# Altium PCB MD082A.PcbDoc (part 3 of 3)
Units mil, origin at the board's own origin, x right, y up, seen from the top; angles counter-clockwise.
Board outline 3650 x 4750 mil, 4 copper layers (Top Layer, GND Layer, Power Layer, Bottom Layer), stack 61.2 mil thick; 201 components, 105 nets, 514 pads, 1209 vias.
Unrouted connection lines stored in the file: 46.
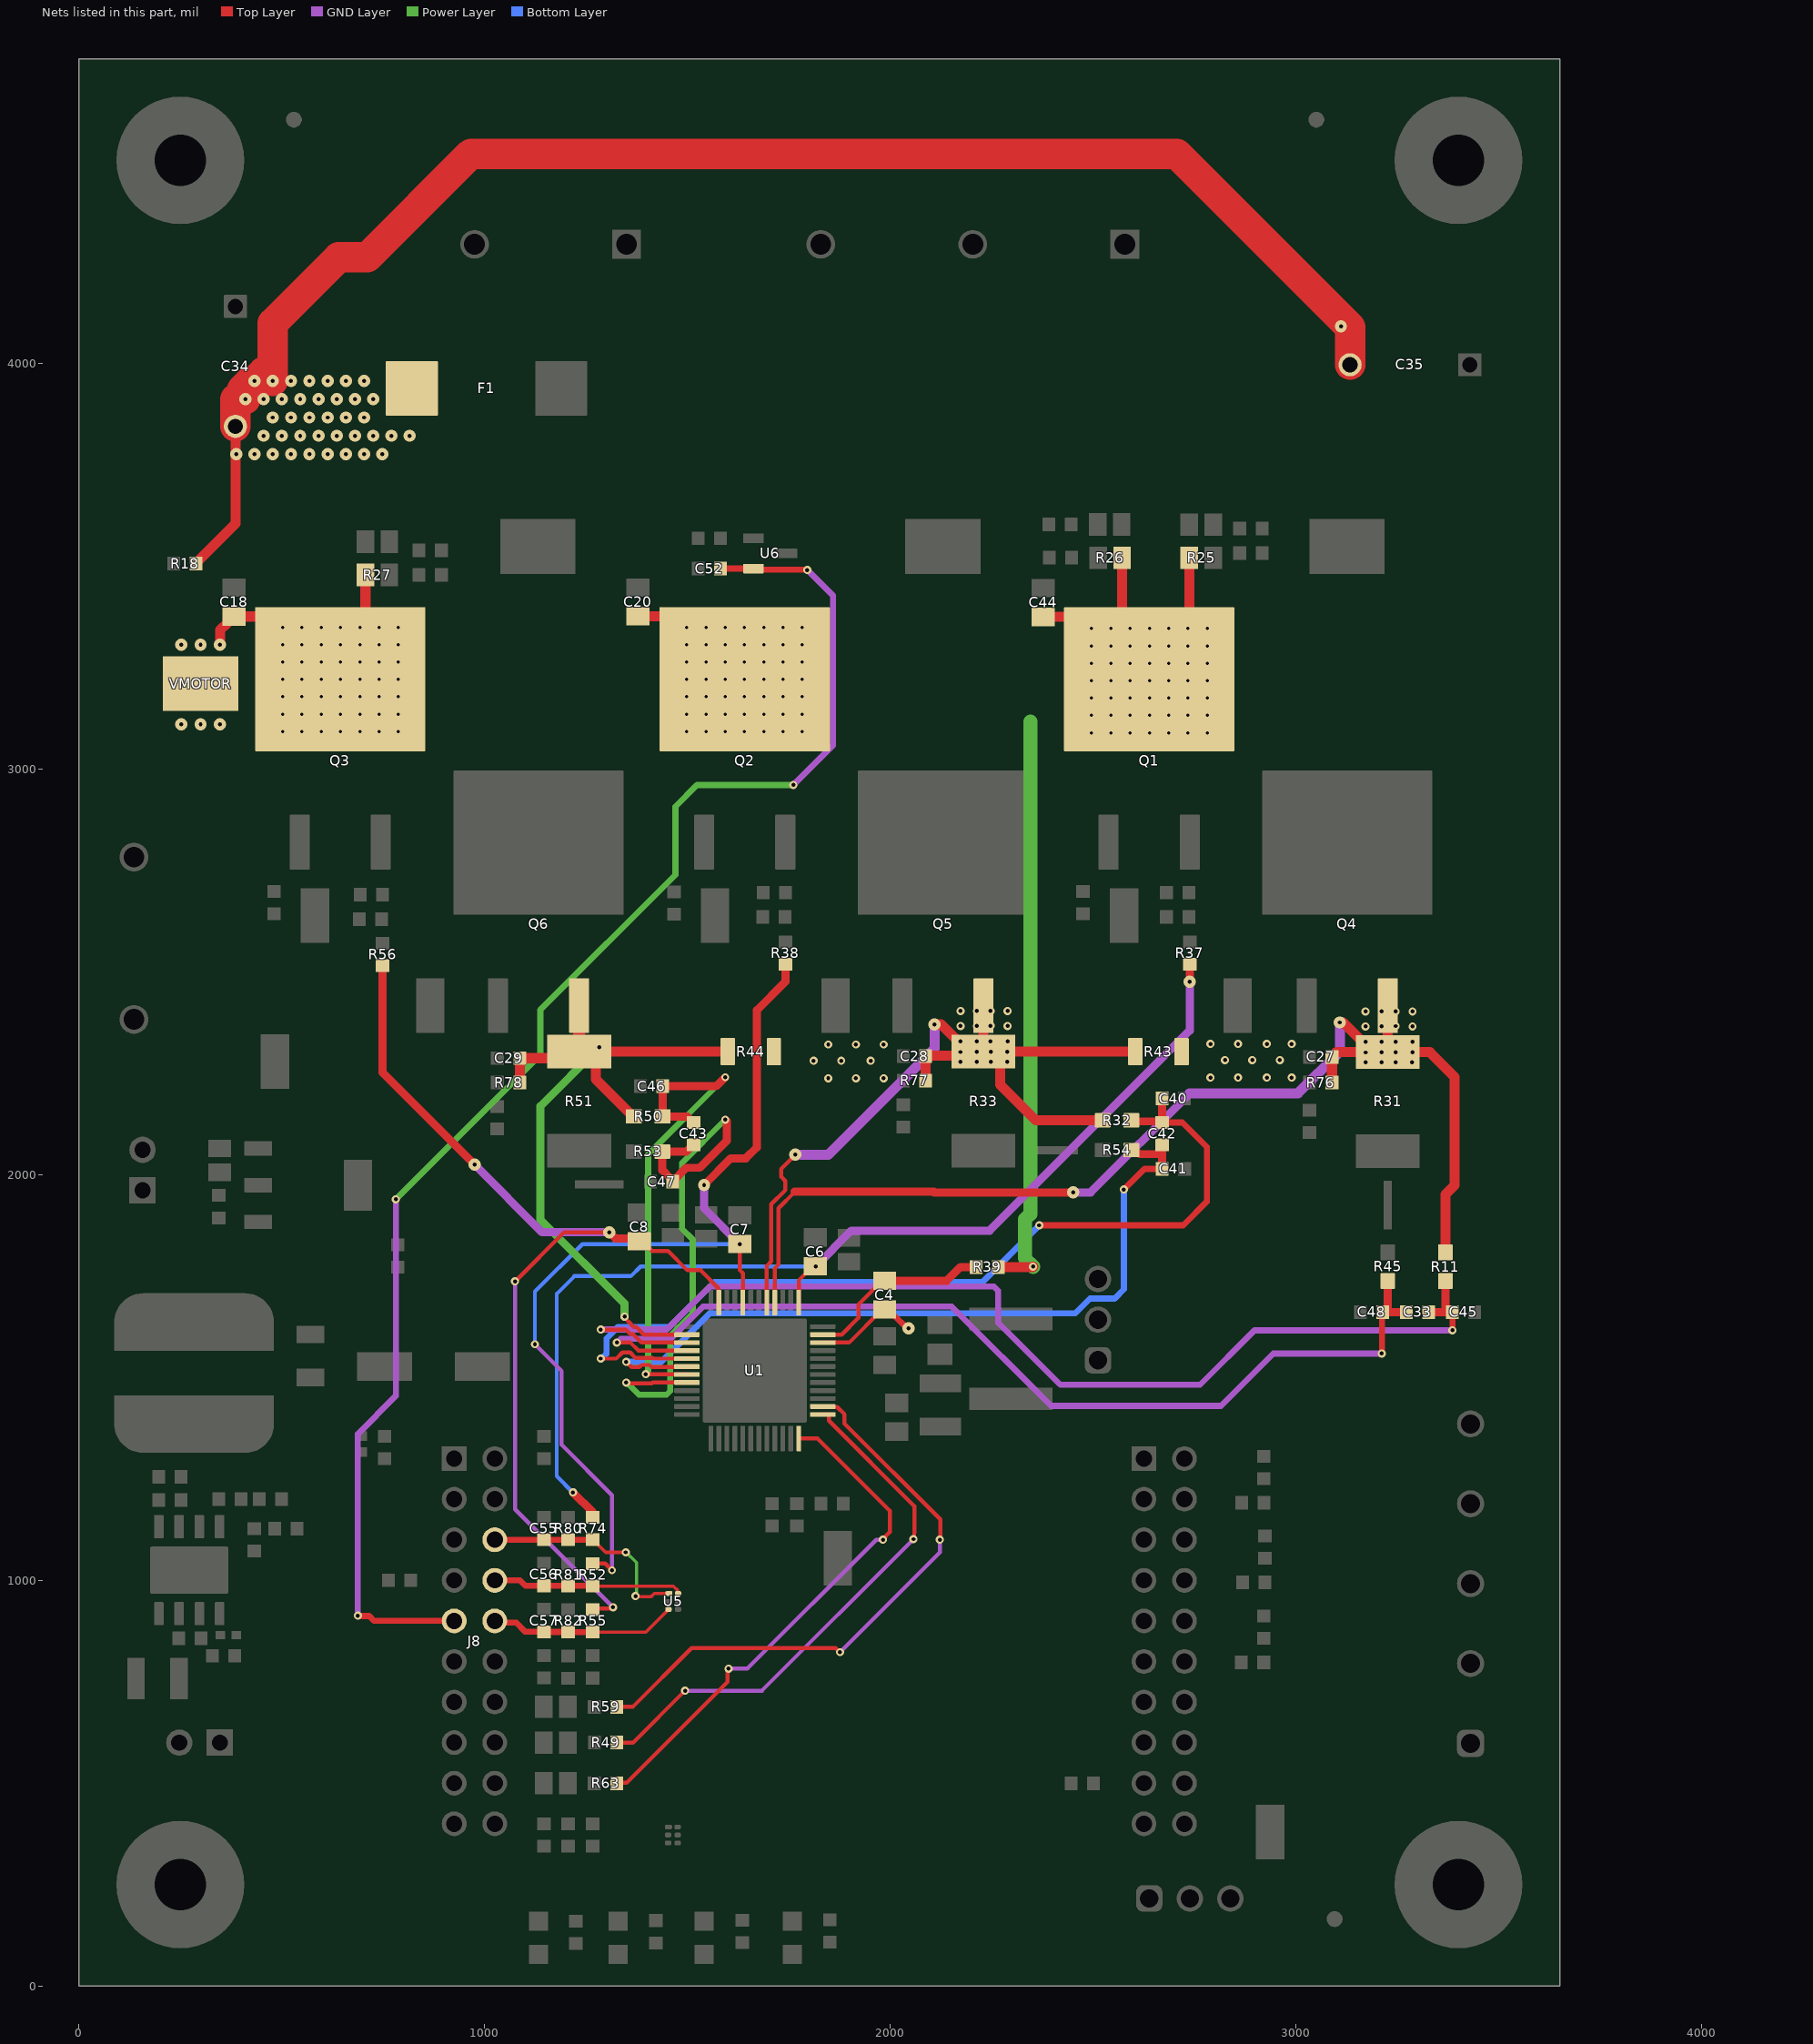
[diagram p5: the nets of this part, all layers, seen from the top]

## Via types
v1: diameter 20, hole 10, Top Layer to Bottom Layer, tented both sides, 424 vias
v2: diameter 30, hole 10, Top Layer to Bottom Layer, tented both sides, 355 vias
v3: diameter 30, hole 7.87, Top Layer to Bottom Layer, tented both sides, 294 vias
v4: diameter 19.68, hole 7.87, Top Layer to Bottom Layer, tented both sides, 76 vias
v5: diameter 20, hole 7.87, Top Layer to Bottom Layer, tented both sides, 54 vias
v6: diameter 19.68, hole 7.87, Top Layer to Bottom Layer, 4 vias
v7: diameter 20, hole 8, Top Layer to Bottom Layer, tented both sides, 1 vias
v8: diameter 30, hole 10, Top Layer to Bottom Layer, 1 vias

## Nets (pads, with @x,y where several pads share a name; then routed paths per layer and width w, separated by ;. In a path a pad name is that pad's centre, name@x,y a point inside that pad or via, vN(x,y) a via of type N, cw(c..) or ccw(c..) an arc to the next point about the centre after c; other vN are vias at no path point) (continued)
SHA: C6.1 R37.1 R74.2 U1.37 | length 2686
  Top Layer w10: U1.37@1775.17,1685.23 U1.37@1774.27,1684.32 1774.27,1739.4 C6.1@1809.24,1774.37
  Top Layer w20: v1(1217.84,1216.61) 1266.49,1167.95 R74.2@1266.49,1155.12 ; v2(2738,2475.67) R37.1@2738,2518.44
  GND Layer w20: v2(1815.77,1773.75) 1903.65,1861.63 2244.58,1861.63 2738,2355.04 v2(2738,2475.67)
  Bottom Layer w10: v1(1217.84,1216.61) 1177.71,1256.74 1177.71,1705.95 1221.4,1749.64 1360.37,1749.64 1384.48,1773.75 v2(1815.77,1773.75)
SHB: C7.1 R38.1 R52.2 U1.44 | length 2352.5
  Top Layer w10: R52.2@1266.49,1041.48 1297.34,1041.48 v1(1314,1024.81) ; v2(1629.31,1828.78) 1629.31,1764.1 1636.47,1756.95 U1.44@1636.47,1684.32
  Top Layer w20: v2(1541,1974) 1607,2040 1644,2040 1671,2067 1671,2405.11 1741.56,2475.67 R38.1@1741.56,2518.44
  GND Layer w10: v1(1123.91,1581.96) 1190,1515.87 1190,1334 1314,1210 v1(1314,1024.81)
  GND Layer w20: v2(1541,1974) 1541,1917.09 v2(1629.31,1828.78)
  Bottom Layer w10: v1(1123.91,1581.96) 1123.91,1711.91 1240.78,1828.78 v2(1629.31,1828.78)
SHC: C8.1 R55.2 R56.1 U1.47 | length 2586.1
  Top Layer w10: v1(1075,1736.71) 1196.29,1858 v2(1307,1858) ; R55.2@1266.49,927.56 1269.82,930.89 1313.67,930.89 v1(1316.53,933.74) ; C8.1@1380.86,1835.78 1398.5,1818.14 1407.11,1818.14 1413.09,1812.15 1451.55,1812.15 1499.57,1764.14 1532.38,1764.14 1576.51,1720.01 1576.51,1685.23 U1.47@1577.42,1684.32
  Top Layer w20: R56.1@748.56,2515.37 748.56,2251.22 v2(975,2024.78) ; v2(1307,1858) 1322.32,1842.68 1373.95,1842.68 C8.1@1380.86,1835.78
  GND Layer w10: v1(1075,1736.71) 1075,1175.27 v1(1316.53,933.74)
  GND Layer w20: v2(975,2024.78) 1141.78,1858 v2(1307,1858)
SLA: C27.2 Q4.3 R11.2 R31.2 R43.1 R76.2 U1.40 | length 2917.6
  Top Layer w10: U1.40@1715.21,1684.32 1715.21,1769.45 1724.35,1778.59 1724.35,1917 1763.99,1956.64 1763.99,1957.75
  Top Layer w20: 1763.99,1957.75 2106.62,1957.75 2108.37,1956 v2(2451,1956)
  Top Layer w25: R76.2@3088.56,2226.56 C27.2@3088.56,2290 3088.56,2290.98 3099.62,2302.05 R31.2@3188.6,2302.05 ; v2(3108,2375) 3115.65,2375 R31.2@3188.6,2302.05 ; Q4.3@3226,2416.43 R31.2@3226,2302.05 ; R11.2@3367.99,1808.31 3367.99,1951.08 3390.94,1974.02 3390.94,2240.62 3329.5,2302.05 R31.2@3226,2302.05 ; R31.2@3188.6,2302.05 R31.2@3226,2302.05
  GND Layer w20: v2(2451,1956) 2493.39,1956 2737.17,2199.78
  GND Layer w25: 2737.17,2199.78 3004.3,2199.78 3108,2303.48 v2(3108,2375)
  other v1: 2789,2239 2857,2239 2928,2239 2989.21,2239 3171,2277 3211,2277.29 3245.5,2276.9 3286,2276.9 2825,2282 2892,2282 2960,2282 3171,2301 3211,2302 3245.5,2302.05 3286.53,2302.05 2789,2322 2857,2322 2928,2322 2989,2322 3171,2327 3211,2327 3245,2327 3287,2327 3171,2365 3211,2365 3287,2365.25 3245,2366 3171,2402 3211,2402 3245,2402 3287,2402
SLB: C28.2 Q5.3 R32.2 R33.2 R43.2 R44.1 R77.2 U1.41 | length 2149.9
  Top Layer w10: U1.41@1695.53,1684.32 1695.53,1775.05 1706.48,1786 1706.48,1926.88 1741.12,1961.52 1741.12,1984.61 1730.96,1994.77 1730.96,2013.96 v2(1766,2049)
  Top Layer w25: R77.2@2087.12,2231.75 C28.2@2087.12,2292 ; C28.2@2087.12,2292.98 2219.44,2292.98 R33.2@2229.5,2303.05 ; v2(2109,2370) 2125.15,2370 2192.1,2303.05 2219.44,2303.05 R33.2@2229.5,2303.05 ; Q5.3@2229.5,2416.43 R33.2@2229.5,2303.05 ; R32.2@2523.09,2133.8 2358.19,2133.8 2270.62,2221.37 2270.62,2274.21 2241.78,2303.05 R33.2@2229.5,2303.05 ; R43.2@2603.58,2303.05 2266.9,2303.05 R33.2@2229.5,2303.05
  GND Layer w25: v2(1766,2049) 1846.95,2049 2109,2311.05 v2(2109,2370)
  other v1: 1847.03,2237.55 1915.31,2237.55 1983.31,2237.55 2173,2278.1 2213,2278.39 2247.5,2278 2288,2278 1811.03,2280.55 1879.03,2280.55 1951.31,2280.55 2173,2302.1 2213,2303.1 2247.5,2303.15 2288.53,2303.15 1847.03,2320.55 1915.31,2320.55 1983.31,2320.55 2173,2328.1 2213,2328.1 2247,2328.1 2289,2328.1 2173,2366.1 2213,2366.1 2289,2366.35 2247,2367.1 2173,2403.1 2213,2403.1 2247,2403.1 2289,2403.1
SLC: C29.2 Q6.3 R44.2 R50.2 R51.2 R78.2 U1.2 | length 1900.8
  Top Layer w10: v1(1345,1650) 1345,1647.29 1361.06,1631.24 1361.06,1630.47 1367.5,1624.02 1374.15,1624.02 1392.59,1605.58 U1.2@1498.68,1605.58
  Top Layer w25: R78.2@1086.56,2226.75 C29.2@1086.56,2287 1216.95,2287 R51.2@1233,2303.05 ; R50.2@1367.84,2143.35 1362.62,2148.57 1360.65,2148.57 1274.13,2235.1 1274.13,2274.21 1245.29,2303.05 R51.2@1233,2303.05 ; R44.2@1599.07,2303.05 1282.75,2303.05 R51.2@1233,2303.05
  Top Layer w30: R51.2@1233,2303.05 Q6.3@1233,2416.43
  Power Layer w20: v1(1282.75,2313.8) 1137.39,2168.44 1137.39,1889.42 1345,1681.81 v1(1345,1650)
SNA: C33.2 C48.1 R45.1 U1.4 | length 2483.1
  Top Layer w10: v1(1326.12,1585.9) 1359.38,1585.9 1378.66,1566.62 1421.28,1566.62 1421.69,1566.21 U1.4@1498.68,1566.21
  Top Layer w15: v1(3211,1559) 3211.96,1559.96 3211.96,1659.66 C48.1@3213.67,1661.37
  Top Layer w20: C48.1@3226,1661.27 3271.85,1661.27 C33.2@3271.95,1661.17 ; C48.1@3226,1661.37 R45.1@3226,1737.64
  GND Layer w15: v1(1326.12,1585.9) 1335.59,1595.37 1458.72,1595.37 1538.35,1675 2151.05,1675 2396.05,1430 2815,1430 2944,1559 v1(3211,1559)
SNB: C41.1 C42.2 R54.1 U1.6 | length 1966.1
  Top Layer w10: v1(1349,1538.65) 1362.2,1525.45 1381.63,1525.45 1387.05,1530.87 1406.47,1530.87 1411.9,1525.45 1462.51,1525.45 1462.99,1525.94 1497.77,1525.94 U1.6@1498.68,1526.84
  Top Layer w15: v1(2575.61,1963.31) 2626.39,2014.09 C41.1@2670.23,2014.09
  Top Layer w20: R54.1@2593.96,2060.39 2601.67,2052.68 2613.1,2052.68 2615.36,2050.41 2660.39,2050.41 C42.2@2670.23,2060.25 ; C41.1@2670.23,2014.09 C42.2@2670.23,2060.25 ; C42.2@2670.23,2073.35 C42.2@2670.23,2060.25
  Bottom Layer w15: v1(1349,1538.65) 1435.46,1538.65 1554.61,1657.8 2455.26,1657.8 2492.18,1694.72 2552.89,1694.72 2575.61,1717.44 v1(2575.61,1963.31)
SNC: C43.2 C47.1 R53.1 U1.8 | length 1421.1
  Top Layer w10: v1(1349,1487.61) 1351.71,1487.61 1354.19,1485.13 1412.01,1485.13 1414.36,1487.47 U1.8@1498.68,1487.47
  Top Layer w20: C43.2@1514.98,2073.34 1513.99,2073.34 1497.56,2056.91 R53.1@1438.21,2056.91 1438.21,2010.81 1458.02,1990.99 1458.02,1988.35 C47.1@1463.77,1982.61 1463.77,1983.59 1497.09,2016.91 1530.08,2016.91 1597.1,2083.93 1597.1,2131.61 v1(1593.17,2135.55)
  Power Layer w10: v1(1349,1487.61) v1@1350.35,1487.61
  Power Layer w15: v1@1350.35,1487.61 1380.46,1457.5 1448.6,1457.5 1457.39,1466.29 1457.39,1602.27 1512.89,1657.77 1512.89,1840.11 1486.61,1866.4 1486.61,2028.99 v1(1593.17,2135.55)
SOA: R59.2 U1.26 | length 1457.8
  Top Layer w10: R59.2@1325.34,688.06 1365.06,688.06 1510,833 1865.14,833 1875.14,823 v1(1876,823) ; U1.26@1833.32,1428.42 1834.23,1427.51 1869.01,1427.51 1886.88,1409.64 1886.88,1386.24 2123,1150.12 v1@2123,1104.72
  GND Layer w10: v1(1876,823) 2122,1069 v1(2122,1100)
SOB: R49.2 U1.25 | length 1348.4
  Top Layer w10: R49.2@1326.12,600 1366,600 v1(1494,728) ; U1.25@1833.32,1408.73 1847.46,1408.73 1848.37,1407.83 1848.37,1393.68 2059,1183.06 2059,1118.19 2058.91,1118.1 2058.91,1103.46 v1(2057,1101.54)
  GND Layer w10: v1(1494,728) 1683.46,728 v1(2057,1101.54)
SOC: R63.2 U1.24 | length 1299.1
  Top Layer w10: R63.2@1325.34,500 1326.55,501.21 1350.23,501.21 1599.13,750.1 1599.13,780.48 v1(1601.04,782.39) ; U1.24@1774.27,1349.68 1820.21,1349.68 1998.46,1171.42 1998.46,1118.7 1981.81,1102.05 v1(1981.81,1100)
  GND Layer w10: v1(1601.04,782.39) 1647.55,782.39 1965.16,1100 v1(1981.81,1100)
SPA: C33.1 C45.1 R11.1 U1.3 | length 2752.4
  Top Layer w10: v1(1286.42,1618.24) 1348,1618.24 1360.1,1606.15 1366.75,1606.15 1387,1585.9 U1.3@1498.68,1585.9
  Top Layer w15: 3367.99,1661.17 C45.1@3373.7,1661.17 ; 3367.99,1666.88 C45.1@3373.7,1661.17 ; v1(3385.34,1616.13) C45.1@3385.34,1661.17 C45.1@3373.7,1661.17
  Top Layer w20: C33.1@3327.06,1661.17 3367.99,1661.17 ; 3367.99,1666.88 R11.1@3367.99,1737.44
  GND Layer w15: v1(1286.42,1618.24) 1449.24,1618.24 1555.09,1724.09 2255.71,1724.09 2265.81,1714 2265.81,1635.19 2419,1482 2763.44,1482 2897.58,1616.13 v1(3385.34,1616.13)
SPB: C40.1 C42.1 R32.1 U1.5 | length 2306.9
  Top Layer w10: v1(1286.42,1546.53) 1324.53,1546.53 1339.53,1561.53 1358.47,1561.53 1371.25,1548.75 1413.88,1548.75 1416.1,1546.53 U1.5@1498.68,1546.53
  Top Layer w15: v1(2367,1875) 2721.87,1875 2780,1933.13 2780,2068.28 2719.81,2128.47 C42.1@2670.23,2128.47 2668.04,2130.65 C42.1@2667.56,2131.13
  Top Layer w20: R32.1@2593.96,2133.8 2596.62,2131.13 C42.1@2667.56,2131.13 ; C42.1@2668.04,2130.65 2669.81,2132.42 2669.81,2187.32 C40.1@2669.4,2187.73
  Bottom Layer w10: v1(1286.42,1546.53) v1@1288.78,1546.53
  Bottom Layer w15: v1@1288.78,1546.53 1300.74,1558.49 1300.74,1596.41 1328.96,1624.63 1455.63,1624.63 1566.23,1735.23 2227.23,1735.23 v1(2367,1875)
SPC: C43.1 C46.1 R50.1 U1.7 | length 1235.3
  Top Layer w10: v1(1397,1508) 1397.42,1507.58 1498.26,1507.58 U1.7@1498.68,1507.16
  Top Layer w20: C43.1@1514.98,2128.46 1513.99,2128.46 1499.1,2143.35 R50.1@1438.71,2143.35 1438.84,2143.49 1438.84,2217.52 C46.1@1438.98,2217.66 1570.66,2217.66 v1(1593,2240)
  Power Layer w15: v1(1397,1508) 1397,1509.35 1403.16,1515.51 1403.16,2050.16 v1(1593,2240)
TEMP: C52.1 J8.9 U6.2 | length 3686
  Top Layer w15: v1(687.61,912.96) 688.56,912.01 715.6,912.01 727.61,900 J8.9@925,900 ; C52.1@1581.47,3493.6 U6.2@1662.66,3493.6 1665.07,3491.19 1794.42,3491.19 v1(1795.38,3490.23)
  GND Layer w15: v1(687.61,912.96) 687.61,1360.65 781.22,1454.26 v1(781.22,1939.22) ; v1(1760.83,2960.27) 1859,3058.44 1859,3426.61 v1(1795.38,3490.23)
  Power Layer w15: v1(781.22,1939.22) 1137.39,2295.4 1137.39,2406 1470.12,2738.73 1470.12,2907 1523.39,2960.27 v1(1760.83,2960.27)
VCP: C4.1 U1.34 | length 264.7
  Top Layer w10: U1.34@1833.32,1585.9 1898.43,1585.9 1980.09,1667.57 C4.1@1986,1667.57
  Top Layer w15: C4.1@1986,1667.57 2001.14,1652.43 2009.82,1652.43 2040.94,1621.31 v8(2045,1621.31)
VDRAIN: C4.2 R39.1 U1.35 | length 466.1
  Top Layer w8: U1.35@1833.32,1605.58 U1.35@1838.27,1605.58
  Top Layer w10: U1.35@1838.27,1605.58 1879.82,1605.58 1921.14,1646.9 1921.14,1679.48 1980.09,1738.43 C4.2@1986,1738.43
  Top Layer w20: C4.2@1986,1738.43 2139.43,1738.43 2173,1772 R39.1@2211.44,1772
VMOTOR: C18.2 C20.2 C34.2 C35.2 C44.2 F1.1 Q1.2 Q2.2 Q3.2 R18.1 R25.2 R26.2 R27.2 R39.2 VMOTOR.1 | length 6242.6
  Top Layer w25: R18.1@288.56,3506 288.56,3506.98 386,3604.43 C34.2@386,3844.36 ; v2(347.5,3306.17) 348.46,3307.12 348.46,3342.02 365.96,3359.52 365.96,3365.43 376.09,3375.57 C18.2@382,3375.57 475.87,3375.57 v3(502.44,3349) ; v3(692.44,3349) 706.3,3362.86 R27.2@706.3,3478 ; C20.2@1378,3376 1471,3376 v3(1498,3349) ; R39.2@2266.56,1772 2350.84,1772 v1(2351.91,1773.07) ; C44.2@2377,3374.57 2467.43,3374.57 v3(2496,3346) ; R26.2@2571.04,3520.55 2571.04,3365.96 v3(2591,3346) ; v3(2733.5,3346) 2736.78,3349.28 R25.2@2736.78,3520.1
  Top Layer w30: Q3.2@520.46,3378.48 v3(549.94,3349)
  Top Layer w75: C34.2@386,3844.36 386,3911 ; v2(410.5,3911) 410.5,3926.63 402.09,3935.04 423.04,3956 v2(433,3956) 455.5,3978.5 ; v2(478,3956) 478,4098.63 640,4260.63 710.66,4260.63 966.04,4516 2705.87,4516 3133,4088.87 C35.2@3133,3996
  Power Layer w35: 2345,3116.05 2345,1903.03 2331.63,1889.65 2331.63,1793.36 v1(2351.91,1773.07)
  other v2: 252.5,3109.95 300,3109.95 347.5,3109.95 252.5,3306.17 300,3306.17 388,3776 433,3776 478,3776 523,3776 568,3776 613,3776 658,3776 703,3776 748,3776 455.5,3821 500.5,3821 545.5,3821 590.5,3821 635.5,3821 680.5,3821 725.5,3821 770.5,3821 815.5,3821 478,3866 523,3866 568,3866 613,3866 658,3866 703,3866 455.5,3911 500.5,3911 545.5,3911 590.5,3911 635.5,3911 680.5,3911 725.5,3911 523,3956 568,3956 613,3956 658,3956 703,3956 3110.5,4091
  other v3: 2496,3089 2543.5,3089 2591,3089 2638.5,3089 2686,3089 2733.5,3089 2781,3089 502.44,3092 549.94,3092 597.44,3092 644.94,3092 692.44,3092 739.94,3092 787.44,3092 1498,3092 1545.5,3092 1593,3092 1640.5,3092 1688,3092 1735.5,3092 1783,3092 2496,3131.83 2543.5,3131.83 2591,3131.83 2638.5,3131.83 2686,3131.83 2733.5,3131.83 2781,3131.83 502.44,3134.83 549.94,3134.83 597.44,3134.83 644.94,3134.83 692.44,3134.83 739.94,3134.83 787.44,3134.83 1498,3134.83 1545.5,3134.83 1593,3134.83 1640.5,3134.83 1688,3134.83 1735.5,3134.83 1783,3134.83 2496,3174.67 2543.5,3174.67 2591,3174.67 2638.5,3174.67 2686,3174.67 2733.5,3174.67 2781,3174.67 502.44,3177.67 549.94,3177.67 597.44,3177.67 644.94,3177.67 692.44,3177.67 739.94,3177.67 787.44,3177.67 1498,3177.67 1545.5,3177.67 1593,3177.67 1640.5,3177.67 1688,3177.67 1735.5,3177.67 1783,3177.67 2496,3217.5 2543.5,3217.5 2591,3217.5 2638.5,3217.5 2686,3217.5 2733.5,3217.5 2781,3217.5 502.44,3220.5 549.94,3220.5 597.44,3220.5 644.94,3220.5 692.44,3220.5 739.94,3220.5 787.44,3220.5 1498,3220.5 1545.5,3220.5 1593,3220.5 1640.5,3220.5 1688,3220.5 1735.5,3220.5 1783,3220.5 2496,3260.33 2543.5,3260.33 2591,3260.33 2638.5,3260.33 2686,3260.33 2733.5,3260.33 2781,3260.33 502.44,3263.33 549.94,3263.33 597.44,3263.33 644.94,3263.33 692.44,3263.33 739.94,3263.33 787.44,3263.33 1498,3263.33 1545.5,3263.33 1593,3263.33 1640.5,3263.33 1688,3263.33 1735.5,3263.33 1783,3263.33 2496,3303.17 2543.5,3303.17 2591,3303.17 2638.5,3303.17 2686,3303.17 2733.5,3303.17 2781,3303.17 502.44,3306.17 549.94,3306.17 597.44,3306.17 644.94,3306.17 692.44,3306.17 739.94,3306.17 787.44,3306.17 1498,3306.17 1545.5,3306.17 1593,3306.17 1640.5,3306.17 1688,3306.17 1735.5,3306.17 1783,3306.17 2543.5,3346 2638.5,3346 2686,3346 2781,3346 597.44,3349 644.94,3349 739.94,3349 787.44,3349 1545.5,3349 1593,3349 1640.5,3349 1688,3349 1735.5,3349 1783,3349
VSENA: C55.2 J8.6 R74.1 R80.2 U5.1 | length 542.6
  Top Layer w8: R74.1@1266.49,1100 1267.48,1100 1298.48,1069 v1(1348,1069) ; v1(1371.87,961.19) 1373.75,959.31 1409.72,959.31 1418.09,967.69 U5.1@1454.17,967.69
  Top Layer w15: J8.6@1025,1100 C55.2@1146,1100 R80.2@1206.25,1100 R74.1@1266.49,1100
  Power Layer w8: v1(1348,1069) 1349,1069 1374.17,1043.83 1374.17,963.49 v1(1371.87,961.19)
VSENB: C56.2 J8.8 R52.1 R81.2 U5.6 | length 469.1
  Top Layer w8: R52.1@1266.49,986.36 1267.39,985.46 1465.63,985.46 1474.91,976.19 1474.91,969.59 U5.6@1476.81,967.69
  Top Layer w15: J8.8@1025,1000 1087.11,1000 1100.63,986.48 1206.12,986.48 R81.2@1206.25,986.36 R52.1@1266.49,986.36
VSENC: C57.2 J8.10 R55.1 R82.2 U5.3 | length 463.9
  Top Layer w8: R55.1@1266.49,872.44 1397.32,872.44 1449.32,924.44 1449.32,926.41 1451.22,928.32 U5.3@1453.19,928.32
  Top Layer w15: J8.10@1025,900 1029.3,895.7 1078.01,895.7 1100.51,873.21 C57.2@1146,873.21 1146.38,872.82 1205.86,872.82 R82.2@1206.25,872.44 R55.1@1266.49,872.44
pads on no net: FID1.1 FID2.1 FID3.1 H1.0 H2.0 H3.0 H4.0 H5.1 H6.1 H7.1 H8.1 J8.3 J8.5 J8.11 J8.15 J9.6 J9.8 J9.10 J9.18 J9.19 J9.20 SH-J1.0 SH-J2.0 SH-J3.0 SH-J4.0 U2.6 U2.9@272,1025 U4.3 U4.4 U4.6

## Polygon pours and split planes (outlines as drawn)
SLB on Power Layer "POWER_LAYER_SLB_P078" (solid, remove dead copper, pour order 78): 2307.5,2431.7 2307.69,2431.51 2307.69,2262.67 2267.46,2222.44 1798.5,2222.44 1798.5,2336.18 1893.12,2430.8
SLA on Power Layer "POWER_LAYER_SLA_P086" (solid, remove dead copper, pour order 86): 3306.55,2262.01 3307,2262.46 3307,2416.89 2827,2416.89 2738.64,2328.54 2738.64,2227 3306.11,2227 3306.55,2226.56
VMOTOR on Power Layer "POWER_LAYER_VMOTOR_P110" (solid, remove dead copper, pour order 110): 308.69,3015 2899,3015 3289,3405 3289,4066 3212,4143 2968,4143 2818,3993 2654,3993 417.84,3993 230,3766.26 230,3071.31
GND on Power Layer "POWER_LAYER_GND_P068" (solid, remove dead copper, pour order 111): 0,4750 3650,4750 3650,0 0,0
MOTC on GND Layer "GND_LAYER_MOTC_P098" (solid, remove dead copper, pour order 98): 733,2556 839,2556 912.75,2629.75 1342.31,2629.75 1363,2650.44 1363,3206 1272,3297 1272,3420 1921,4069 1921,4314 1859,4376 1691,4376 878,3563 878,2836 767,2725 739,2725 733,2719
MOTA on GND Layer "GND_LAYER_MOTA_P100" (solid, remove dead copper, pour order 100): 2708,2558 2835.67,2558 2912.43,2634.75 3342.59,2634.75 3346.28,2638.45 3346.28,3657.22 2638,4365.5 2534.34,4365.5 2510.16,4341.32 2510.16,4005.84 2900.5,3615.5 2900.5,3024.22 2769.28,2893 2708,2893
MOTB on GND Layer "Top Layer-No Net" (solid, remove dead copper, pour order 99): 1838.27,2558 1915.03,2634.75 2348.38,2634.75 2355.07,2641.44 2355.07,3279.1 2328,3306.17 2328,3466 2343.1,3481.1 2391.7,3481.1 2407,3496.41 2407,3626.99 2387.92,3646.07 2387.92,3735.42 2387.92,4301.08 2307.68,4381.32 2091.49,4381.32 1974,4263.82 1974,4047.64 1919,3992.64 1919,3007 1819,2907 1722.16,2907 1718,2902.84 1718,2745.03 1725.07,2736.48 1725.07,2565.49 1721.86,2558
GND on GND Layer "GND_LAYER_GND_P066" (solid, remove dead copper, pour order 101): 0,4750 3650,4750 3650,0 0,0
GND on Bottom Layer "BOTTOM_LAYER_GND_P087" (solid, remove dead copper, pour order 87): -5.37,4724.31 3644.63,4724.31 3644.63,-25.69 -5.37,-25.69
VMOTOR on Bottom Layer "BOTTOM_LAYER_VMOTOR_P082" (solid, remove dead copper, pour order 82): 308.69,3015 2899,3015 3289,3405 3289,4066 3212,4143 2968,4143 2818,3993 2654,3993 434.29,3993 234,3770.7 234,3068.45
SLB on Top Layer "TOP_LAYER_SLB_P090" (solid, remove dead copper, pour order 90): 1695.53,2255.59 1733.46,2217.66 1975.52,2217.66 2006.18,2248.31 2005.74,2248.75 2005.74,2338.89 1697.38,2338.89 1695.53,2337.04
GND on Top Layer "GND_LAYER_GND_P066" (solid, remove dead copper, pour order 109): 0,4750 3650,4750 3650,0 0,0
SLB on Top Layer "TOP_LAYER_SLB_P091" (solid, remove dead copper, pour order 91): 2301.21,2343 2580.95,2343 2587.75,2336.2 2587.75,2270.01 2586.65,2270.01 2555.64,2239 2301.21,2239
SLA on Top Layer "TOP_LAYER_SLA_P092" (solid, remove dead copper, pour order 92): 2700.79,2270.01 2700.79,2254.01 2728.25,2226.56 3006.51,2226.56 3008.38,2228.43 3008.38,2338.69 3008.07,2339 2701,2339
SLA on Top Layer "TOP_LAYER_SLA_P093" (solid, remove dead copper, pour order 93): 3200.78,2483.7 3147,2429.91 3147,2337.51 3303.49,2337.51 3304,2337 3304,2430.7 3251,2483.7 3200.98,2483.7 3200.78,2483.89
SLB on Top Layer "TOP_LAYER_SLB_P094" (solid, remove dead copper, pour order 94): 2204.28,2484.7 2150.5,2430.91 2150.5,2338.51 2306.99,2338.51 2307.5,2338 2307.5,2431.7 2254.5,2484.7 2204.48,2484.7 2204.28,2484.89
SLC on Top Layer "TOP_LAYER_SLC_P102" (solid, remove dead copper, pour order 102): 1207.78,2484.7 1154,2430.91 1154,2338.51 1310.49,2338.51 1311,2338 1311,2431.7 1258,2484.7 1207.98,2484.7 1207.78,2484.89
SLC on Top Layer "TOP_LAYER_SLC_P089" (solid, remove dead copper, pour order 89): 1310.49,2383.49 1535.96,2383.49 1583.25,2336.2 1583.25,2270.01 1582.14,2270.01 1574.8,2262.67 1310.49,2262.67
VMOTOR on Top Layer "TOP_LAYER_VMOTOR_P103" (solid, remove dead copper, pour order 103): 886,4009 446.49,4009 319.09,3881.6 319.09,3792.23 355.31,3756 778.51,3756 882.75,3860.25
VMOTOR on Top Layer "TOP_LAYER_VMOTOR_P104" (solid, remove dead copper, pour order 104): 227.52,3327.52 191,3291 191,3129 232,3088 363,3088 405,3130 405,3302 380.53,3326.47
MOTC on Top Layer "TOP_LAYER_MOTC_P105" (solid, remove dead copper, pour order 105): 723.44,2556 839,2556 912.75,2629.75 1342.31,2629.75 1363,2650.44 1363,3206 1272,3297 1272,3420 1921,4069 1921,4314 1859,4376 1691,4376 878,3563 878,3043 723.44,2888.44
MOTB on Top Layer "Top Layer-MOTB" (solid, remove dead copper, pour order 107): 1838.27,2558 1915.03,2634.75 2348.38,2634.75 2355.07,2641.44 2355.07,3279.1 2328,3306.17 2328,3466 2343.1,3481.1 2391.7,3481.1 2407,3496.41 2407,3626.99 2387.92,3646.07 2387.92,3735.42 2387.92,4301.08 2307.68,4381.32 2091.49,4381.32 1974,4263.82 1974,4047.64 1919,3992.64 1919,3007 1819,2907 1722.16,2907 1718,2902.84 1718,2745.03 1725.07,2736.48 1725.07,2558
MOTA on Top Layer "TOP_LAYER_MOTA_P108" (solid, remove dead copper, pour order 108): 2708,2558 2835.67,2558 2912.43,2634.75 3342.59,2634.75 3346.28,2638.45 3346.28,3657.22 2638,4365.5 2534.34,4365.5 2510.16,4341.32 2510.16,4005.84 2900.5,3615.5 2900.5,3024.22 2769.28,2893 2708,2893

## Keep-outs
Keep-Out Layer:
  text ".Layer_Name" at 577,-858.49 h60

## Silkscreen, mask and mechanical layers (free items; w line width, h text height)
Top Overlay:
  circle w12: c848.76,1377.9 r5.51
  circle w12: c2550.97,1364.3 r5.51
  lines w10: 879,341 1072.03,340.03 1072.5,340.5 1072.5,1359.5 1072,1360 879,1360 879,342 ; 2577.5,339.03 2770.53,338.05 ; 2577.5,340.03 2577.5,1358.03 2770.5,1358.03 ; 2578.46,1625.37 2607.3,1625.37 2607.73,1527.79 2578.73,1527.79 ; 2578.46,1740.58 2607.3,1740.58 2607.73,1643 2578.73,1643 ; 2620.09,156.4 2620.09,127.4 2717.66,127.83 2717.66,156.67 ; 2758.91,155.1 2758.91,126.1 2856.49,126.52 2856.49,155.36 ; 2771,338.53 2771,1357.53
  text "GND" at 923.2,4034.86 h35
  text "VMOTOR" at 1243.2,4034.86 h35
  text "MOTC" at 1771.15,4031.86 h35
  text "MOTB" at 2148.15,4031.86 h35
  text "MOTA" at 2516,4032.22 h35
  text "ABS MAX: 30A" at 1433,3936.03 h35
  text "PVDD SEL" at 2594.01,1783.96 h30
  text "PVDD" at 2630.6,1682.11 h30
  text "PVDD BUCK" at 2630.04,1562.28 h30
  text "J8" at 879,1387 h30
  text "J9" at 2592,1384 h30
  text "GND" at 3104,1369 h30
  text "HALL_C" at 3011.83,1179.05 h30
  text "HALL_B" at 3011.83,994.17 h30
  text "HALL_A" at 3011.83,795.92 h30
  text "HALL_PWR" at 2960.24,581.42 h30
  text "HALL" at 2412.14,205.33 h40
  text "PWR" at 2412.14,146.33 h40
  text "SEL" at 2412.14,88.33 h40
  text "3.3V" at 2572,70 h40
  text "5V" at 2779.39,70 h40
  text "'.PRJ_Number'.PCB_Rev" at 467.58,60 h70
  text ".Layer_Name" at 577,-858.49 h60
Bottom Overlay:
  text ".Layer_Name" at 577,-858.49 h60
Top Paste:
  text ".Layer_Name" at 577,-858.49 h60
Bottom Paste:
  text ".Layer_Name" at 577,-858.49 h60
Top Solder:
  text ".Layer_Name" at 577,-858.49 h60
  text ".Layer_Name" at 577,-858.49 h60
Solder Side:
  text ".Layer_Name" at 577,-858.49 h60
Drill Guide:
  text ".Layer_Name" at 577,-858.49 h60
M1 Board Outline:
  the board outline again, w10
  text ".Layer_Name" at 577,-858.49 h60
M2 Board Dimensions:
  rectangle: 0,-275 125,-150
  rectangle: 125,-400 500,-275
  lines w7: 0,-275 1000,-275 ; 125,-400 125,-150 ; 250,-400 250,-150 ; 500,-400 500,-150 ; 750,-400 750,-150 ; 0,-400 1000,-400 1000,-150 0,-150 0,-400
  text ".Layer_Name" at 577,-858.49 h60
M3 3D STEP Top:
  text ".Layer_Name" at 577,-858.49 h60
M4 3D STEP Bottom:
  text ".Layer_Name" at 577,-858.49 h60
M5 Assembly Top:
  lines w10: -292,-930.17 6308,-930.17 ; -292,-726.83 6310,-726.83 ; -292,-523.5 -292,-1133.5 3713,-1133.5 6310,-1133.5 6310,-523.5 -291.5,-523.5 -291.5,-1133.5 1284,-1133.5 ; 2173,-1133.5 2173,-523.5 ; 3440,-726.83 3440,-523.5 ; 4280,-726.83 4280,-523.5 ; 4902,-1140 4902,-937.17
  text "COMPONENTS MARKED 'DNP' SHOULD NOT BE POPULATED." at 1153.5,-318.5 h60
  text "ASSEMBLY VARIANT:" at 1153,-434 h60
  text ".VariantName" at 2189,-434 h60
  text "PCB VIEWED FROM TOP SIDE" at -228.5,-655.67 h60
  text "BOARD #:" at 2248,-655.67 h60
  text ".PRJ_Number" at 2793.5,-655.67 h60
  text "REV:" at 3638,-655.67 h60
  text ".PCB_Rev" at 3929.5,-655.67 h60
  text "SVN REV:" at 4476,-655.67 h60
  text ".VersionControl_RevNumber" at 4982,-655.67 h60
  text "TID #:" at 2248,-859 h60
  text ".TID" at 2793.5,-859 h60
  text "PLOT NAME =" at -228.5,-1064.34 h60
  text ".plot_File_Name" at 577,-1064.34 h60
  text "GENERATED    :" at 2250,-1064.34 h60
  text ".Print_Date" at 3119.5,-1064.34 h60
  text ".Print_Time" at 3848.5,-1064.34 h60
  text "TEXAS INSTRUMENTS" at 5113,-1064.34 h60
M6 Assembly Bottom:
  lines w10: -292.5,-727.33 6309.5,-727.33 ; -290.5,-930.67 6309.5,-930.67 ; 1115.5,-1140.5 1115.5,-937.67 ; 1737.5,-727.33 1737.5,-524 ; 2577.5,-727.33 2577.5,-524 ; 3844.5,-1134 3844.5,-524 ; 4733.5,-1134 6309,-1134 6309,-524 -292.5,-524 -292.5,-1134 2304.5,-1134 6309.5,-1134 6309.5,-524
  text "COMPONENTS MARKED 'DNP' SHOULD NOT BE POPULATED." at 6102,-318 h60
  text ".VariantName" at 5058,-434 h60
  text "ASSEMBLY VARIANT:" at 6097,-434 h60
  text ".VersionControl_RevNumber" at 1035.5,-656.17 h60
  text "SVN REV:" at 1541.5,-656.17 h60
  text ".PCB_Rev" at 2088,-656.17 h60
  text "REV:" at 2379.5,-656.17 h60
  text ".PRJ_Number" at 3224,-656.17 h60
  text "BOARD #:" at 3769.5,-656.17 h60
  text "PCB VIEWED FROM BOTTOM SIDE" at 6246,-656.17 h60
  text ".TID" at 3224,-859.5 h60
  text "TID #:" at 3769.5,-859.5 h60
  text "TEXAS INSTRUMENTS" at 904.5,-1064.84 h60
  text ".Print_Time" at 2169,-1064.84 h60
  text ".Print_Date" at 2898,-1064.84 h60
  text "GENERATED    :" at 3767.5,-1064.84 h60
  text ".plot_File_Name" at 5440.5,-1064.84 h60
  text "PLOT NAME =" at 6246,-1064.84 h60
M9 Title Sheet:
  drawing of 57 lines, arcs and shapes, not listed
  text "1" at 739.84,8036.5 h70
  text "2" at 3235.5,8036.5 h70
  text "3" at 5724.84,8036.5 h70
  text "4" at 8231.51,8036.5 h70
  text "5" at 10730.5,8036.5 h70
  text "6" at 13235.5,8036.5 h70
  text "A" at -416.5,6893.5 h70
  text "A" at 14383.5,6893.5 h70
  text "B" at -416.5,4513.5 h70
  text "B" at 14383.5,4513.5 h70
  text "C" at -416.5,2138.5 h70
  text "C" at 14383.5,2138.5 h70
  text "PROJECT TITLE:" at 11343.5,277.5 h45
  text ".PRJ_Title" at 11393.5,144.17 h70
  text "DESIGNED FOR:" at 11343.5,-23.5 h45
  text ".PRJ_Customer" at 11393.5,-163.5 h70
  text "D" at -416.5,-231.5 h70
  text "D" at 14383.5,-231.5 h70
  text "FILE NAME:" at 11343.5,-323.5 h45
  text ".PCB_File_Name_No_Path" at 11393.5,-443.5 h70
  text "Texas Instruments (TI) and/or its licensors do not warrant the accuracy or completeness of this specification" at 6374,-605.34 h45
  text "ENGINEER:" at 11343.5,-613.5 h45
  text "LAYOUT BY:" at 12848.5,-613.5 h45
  text "or any information contained therein. TI and/or its licensors do not warrant that this design will meet" at 6329.01,-718 h45
  text ".PRJ_Engineer" at 11393.5,-768.49 h70
  text ".PCB_Layout" at 12899,-768.49 h70
  text "the specifications, will be suitable for your application or fit for any particular purpose, or will operate in" at 6329.01,-830.67 h45
  text ".Layer_Name" at 577,-858.49 h60
  text "ALTIUM DESIGNER VERSION:" at 12848.5,-923.5 h45
  text "an implementation. TI and/or its licensors do not warrant that the design is production worthy. You should" at 6329.01,-943.33 h45
  text "completely validate and test your design implementation to confirm the system functionality for your application." at 6374,-1056 h45
  text ".print_Scale" at 11393.5,-1056.83 h70
  text ".Application_BuildNumber" at 12899,-1056.83 h70
  text "1" at 739.84,-1263.5 h70
  text "2" at 3235.5,-1263.5 h70
  text "3" at 5724.84,-1263.5 h70
  text "4" at 8231.51,-1263.5 h70
  text "5" at 10730.5,-1263.5 h70
  text "6" at 13235.5,-1263.5 h70
M10 Fab Notes:
  drawing of 189 lines, arcs and shapes, not listed
  text "DESIGN INFORMATION" at 12382.02,6356.17 h60
  text "MIN. TRACK WIDTH:" at 11737.46,6224.05 h60
  text "8" at 12833.7,6224.05 h60
  text "MIL" at 12988.46,6224.05 h60
  text "MIN. CLEARANCE:" at 11737.46,6099.92 h60
  text "0.2" at 12773.7,6099.93 h60
  text "mm" at 12988.46,6099.92 h60
  text "MIN. VIA PAD SIZE:" at 11737.46,5975.8 h60
  text "24" at 12803.71,5975.8 h60
  text "MIL" at 12988.46,5975.8 h60
  text "0.05mm (2MIL)" at 12432.46,5845.9 h60
  text "MINIMUM ANNULAR RING" at 11408.23,5837.67 h60
  text "EXTERNAL" at 13140.46,5837.67 h60
  text "PER" at 11608.23,5727.55 h60
  text "IPC-D-275 CLASS 2 LEVEL C" at 11828.23,5727.54 h60
  text "MIL, HOLES" at 13316.46,5627.07 h60
  text "+/-" at 12924,5618.48 h60
  text "+/-" at 13778,5618.48 h60
  text "REGISTRATION TOLERANCES:" at 11408.23,5617.42 h60
  text "METAL" at 12608,5617.42 h60
  text "5" at 13184.2,5617.42 h60
  text "3" at 14017.2,5617.42 h60
  text "MIL" at 14133.46,5617.42 h60
  text "HOLE SIZE TOLERANCE (UNLESS OTHERWISE SPECIFIED):" at 11408.23,5519.1 h60
  text "+/-" at 13778,5516.23 h60
  text "3" at 14017.2,5515.17 h60
  text "MIL" at 14133.46,5515.17 h60
  text "MATERIAL:" at 11333.46,5377.52 h60
  text "FR-4 High Tg" at 12319.9,5249 h60
  text "X" at 12175.46,5241.01 h60
  text "FR-408" at 11754.46,5236.49 h60
  text "OTHER" at 13242.46,5236.49 h60
  text "62 MIL (1.6mm) +/-10%" at 12074.56,5093.46 h60
  text "X" at 11954.46,5091.01 h60
  text "THICKNESS:" at 11408.23,5085.24 h60
  text "OTHER" at 13359.46,5085.24 h60
  text "TOLERANCE:" at 11408.23,4946.92 h60
  text "X" at 12256.46,4946.92 h60
  text "ANSI IPC-6012 TYPE 3 CLASS 2" at 12434.48,4946.92 h60
  text "OTHER +/-" at 12434.46,4802.73 h60
  text "BOW & TWIST:" at 11408.23,4657.54 h60
  text "X" at 12256.46,4657.54 h60
  text "ANSI IPC-6012 TYPE 3 CLASS 2" at 12434.48,4657.54 h60
  text "OTHER +/-" at 12434.46,4510.85 h60
  text "DRILLING:" at 11333.46,4380.23 h60
  text "NC_DRILL FILES" at 13094.46,4275.04 h60
  text "REFERENCE:" at 11408.23,4271.1 h60
  text "X" at 12065.46,4271.01 h60
  text "AS SHOWN" at 12243.46,4271.1 h60
  text "X" at 12966.46,4271.1 h60
  text "OTHER" at 13392.46,4128.85 h60
  text "PTH COPPER THICKNESS:" at 11407.91,4125.32 h60
  text "X" at 12547.14,4125.32 h60
  text "20-30 um" at 12675.14,4125.32 h60
  text "BOARD FINISH:" at 11333.46,3977.73 h60
  text "SILKSCREEN:" at 11488.68,3867.6 h60
  text "X" at 12446.46,3867.6 h60
  text "TOP" at 12563.46,3867.6 h60
  text "X" at 12956.46,3867.6 h60
  text "BOTTOM" at 13074.46,3867.6 h60
  text "SILKSCREEN COLOR:" at 11488.68,3712.41 h60
  text "X" at 12445.46,3712.41 h60
  text "WHITE" at 12563.46,3712.41 h60
  text "OTHER" at 13074.46,3712.41 h60
  text "X" at 12576.46,3568.96 h60
  text "GREEN" at 12694.46,3568.96 h60
  text "OTHER" at 13312.46,3568.96 h60
  text "SOLDER RESIST COLOR:" at 11488.68,3562.1 h60
  text "X" at 12576.46,3414.71 h60
  text "MATTE" at 12694.46,3414.71 h60
  text "SEMI-GLOSS" at 13312,3414.07 h60
  text "IMMERSION GOLD (ENIG)" at 12394.46,3241.94 h60
  text "ENEPIG" at 13732,3234.72 h60
  text "SURFACE FINISH:" at 11333.46,3233.72 h60
  text "X" at 12216.46,3233.72 h60
  text "IMM. TIN/SILVER OR EQUIV" at 11663,3096.4 h60
  text "OTHER" at 13094.46,3092.47 h60
  text "ARRAY/PANEL:" at 11333.46,2937.09 h60
  text "CUT AND TRIM PER M1 BOARD OUTLINE" at 12394.46,2928.87 h60
  text "N.C. ROUTE" at 12394.46,2792.9 h60
  text "X" at 13082.46,2792.9 h60
  text "V. SCORE" at 13260.46,2792.9 h60
  text "CERTIFICATION:" at 11333.46,2663.77 h60
  text "MATERIALS AND WORKMANSHIP FOR ALL PCBS" at 12058.46,2663.77 h60
  text "TO MEET OR EXCEED THE REQUIREMENTS OF:" at 12058.46,2569.71 h60
  text "X" at 11695.97,2441.08 h60
  text "ANSI IPC-A-600F CLASS ->" at 11823.96,2441.08 h60
  text "X" at 13471.97,2441.08 h60
  text "2" at 13581.96,2441.08 h60
  text "1" at 13266.96,2439.58 h60
  text "3" at 13935.96,2439.58 h60
  text "X" at 12507.97,2293.39 h60
  text "RoHS" at 12635.96,2293.39 h60
  text "OTHER" at 13280.36,2293.39 h60
  text "PER ORDER" at 13677.42,2293.39 h60
  text "ALL BOARDS MUST MEET OR EXCEED UL94-V0 REQUIREMENTS." at 11361,2139.57 h60
  text "PCB MUST BEAR THE UL94V-0 UL REGISTERED MATERIAL ID NUMBER" at 11361,2023.5 h60
  text "ADDITIONAL REQUIREMENTS:" at 11333.46,1854.08 h60
  text "MICROSECTION:" at 11408.23,1746.95 h60
  text "YES" at 12313.96,1746.95 h60
  text "REQUIRED" at 13175.46,1602.62 h60
  text "BARE BOARD ELEC. TEST:" at 11408.23,1599.76 h60
  text "NONE" at 12713.96,1599.76 h60
  text "X" at 13057.46,1599.76 h60
  text "PER ORDER" at 13767.46,1599.76 h60
  text "XX MIL VIAS REQUIRE NON-CONDUCTIVE FILL AND PLANARIZE" at 11576.38,1394.82 h59
  text "XX MIL VIAS REQUIRE CONDUCTIVE FILL AND PLANARIZE" at 11584.38,1290.84 h60
  text "OUTER XX MIL TRACES REQUIRE 50 OHM SINGLE-ENDED IMPEDANCE" at 11583.39,1127.46 h58
  text "LAYER 2 & 3 (INNER LAYERS) XX MIL WIDE, XX MIL SPACE / TRACES REQUIRE 100 OHM DIFFERENTIAL IMPEDANCE" at 11575.39,891.74 h60
  text ".Layer_Name" at 577,-858.49 h60
M11 Gerber Information:
  lines w10: -292,-930.17 6308,-930.17 ; -292,-726.83 6310,-726.83 ; -292,-523.5 -292,-1133.5 3713,-1133.5 6310,-1133.5 6310,-523.5 -291.5,-523.5 -291.5,-1133.5 1284,-1133.5 ; 2173,-1133.5 2173,-523.5 ; 3440,-726.83 3440,-523.5 ; 4280,-726.83 4280,-523.5 ; 4902,-1140 4902,-937.17
  text "ALL ARTWORK VIEWED FROM TOP SIDE" at -228.5,-655.67 h60
  text "BOARD #:" at 2248,-655.67 h60
  text ".PRJ_Number" at 2793.5,-655.67 h60
  text "REV:" at 3638,-655.67 h60
  text ".PCB_Rev" at 3929.5,-655.67 h60
  text "SVN REV:" at 4476,-655.67 h60
  text ".VersionControl_RevNumber" at 4982,-655.67 h60
  text "LAYER NAME =" at -228.5,-858.49 h60
  text "TID #:" at 2248,-859 h60
  text ".TID" at 2793.5,-859 h60
  text "PLOT NAME =" at -228.5,-1064.34 h60
  text ".plot_File_Name" at 577,-1064.34 h60
  text "GENERATED    :" at 2250,-1064.34 h60
  text ".Print_Date" at 3119.5,-1064.34 h60
  text ".Print_Time" at 3848.5,-1064.34 h60
  text "TEXAS INSTRUMENTS" at 5113,-1064.34 h60
M12 Stackup:
  drawing of 295 lines, arcs and shapes, not listed
  text "Layer" at 6509.09,7318.5 h60
  text "Name" at 6919,7318.5 h60
  text "Material" at 7848.74,7318.5 h60
  text "Thickness" at 8708.51,7318.5 h60
  text "Constant" at 9358.35,7318.5 h60
  text "Board Layer Stack" at 9928.21,7318.5 h60
  text "1" at 6509.09,7198.5 h60
  text "Top Overlay" at 6919,7198.5 h60
  text "2" at 6509.09,7078.5 h60
  text "Top Solder" at 6919,7078.5 h60
  text "Solder Resist" at 7848.74,7078.5 h60
  text "0.40mil" at 8708.51,7078.5 h60
  text "3.5" at 9358.35,7078.5 h60
  text "3" at 6509.09,6958.5 h60
  text "Top Layer" at 6919,6958.5 h60
  text "Copper" at 7848.74,6958.5 h60
  text "2.80mil" at 8708.51,6958.5 h60
  text "4" at 6509.09,6838.5 h60
  text "Dielectric 2" at 6919,6838.5 h60
  text "FR-4 High Tg" at 7848.74,6838.5 h60
  text "10.00mil" at 8708.51,6838.5 h60
  text "4.8" at 9358.35,6838.5 h60
  text "5" at 6509.09,6718.5 h60
  text "GND Layer" at 6919,6718.5 h60
  text "Copper" at 7848.74,6718.5 h60
  text "1.40mil" at 8708.51,6718.5 h60
  text "6" at 6509.09,6598.5 h60
  text "Dielectric 1" at 6919,6598.5 h60
  text "FR-4 High Tg" at 7848.74,6598.5 h60
  text "32.80mil" at 8708.51,6598.5 h60
  text "4.2" at 9358.35,6598.5 h60
  text "7" at 6509.09,6478.5 h60
  text "Power Layer" at 6919,6478.5 h60
  text "Copper" at 7848.74,6478.5 h60
  text "1.40mil" at 8708.51,6478.5 h60
  text "8" at 6509.09,6358.5 h60
  text "Dielectric 3" at 6919,6358.5 h60
  text "FR-4 High Tg" at 7848.74,6358.5 h60
  text "10.00mil" at 8708.51,6358.5 h60
  text "4.8" at 9358.35,6358.5 h60
  text "9" at 6509.09,6238.5 h60
  text "Bottom Layer" at 6919,6238.5 h60
  text "Copper" at 7848.74,6238.5 h60
  text "2.80mil" at 8708.51,6238.5 h60
  text "10" at 6509.09,6118.5 h60
  text "Solder Side" at 6919,6118.5 h60
  text "Solder Resist" at 7848.74,6118.5 h60
  text "0.40mil" at 8708.51,6118.5 h60
  text "3.5" at 9358.35,6118.5 h60
  text "11" at 6509.09,5998.5 h60
  text "Bottom Overlay" at 6919,5998.5 h60
  text ".Layer_Name" at 577,-858.49 h60
M13 Component Bodies Top:
  text ".Layer_Name" at 577,-858.49 h60
M14 Component Bodies Bottom:
  text ".Layer_Name" at 577,-858.49 h60
M15 Courtyards Top:
  text ".Layer_Name" at 577,-858.49 h60
M16 Courtyards Bottom:
  text ".Layer_Name" at 577,-858.49 h60
Drill Drawing:
  circle w10: c5363.72,3363.96 r16.58
  circle w10: c5363.72,3363.96 r27.63
  circle w10: c5363.72,3239.64 r27.63
  lines w10: 5336.09,2245.08 5363.72,2217.45 5391.34,2245.08 5363.72,2272.71 5336.09,2245.08 ; 5336.09,2341.77 5391.34,2341.77 5391.34,2397.03 5336.09,2397.03 5336.09,2341.77 ; 5336.09,2466.09 5391.34,2466.09 5391.34,2521.35 5336.09,2521.35 5336.09,2466.09 ; 5336.09,2590.41 5336.09,2604.23 5349.9,2618.04 5336.09,2631.85 5336.09,2645.67 5349.9,2645.67 5363.72,2631.85 5377.53,2645.67 5391.34,2645.67 5391.34,2631.85 5377.53,2618.04 5391.34,2604.23 5391.34,2590.41 5377.53,2590.41 5363.72,2604.23 5349.9,2590.41 5336.09,2590.41 ; 5336.09,2714.73 5363.72,2728.55 5391.34,2714.73 5377.53,2742.36 5391.34,2769.99 5363.72,2756.17 5336.09,2769.99 5349.9,2742.36 5336.09,2714.73 ; 5336.09,2852.87 5349.9,2852.87 5349.9,2839.05 5377.53,2839.05 5377.53,2852.87 5391.34,2852.87 5391.34,2880.49 5377.53,2880.49 5377.53,2894.31 5349.9,2894.31 5349.9,2880.49 5336.09,2880.49 5336.09,2852.87 ; 5336.09,3018.63 5391.34,3018.63 5363.72,2963.37 5336.09,3018.63 ; 5336.09,3142.95 5391.34,3142.95 5363.72,3087.69 5336.09,3142.95 ; 5336.09,3460.65 5363.72,3474.47 5391.34,3460.65 5377.53,3488.28 5391.34,3515.91 5363.72,3502.09 5336.09,3515.91 5349.9,3488.28 5336.09,3460.65 ; 5347.14,2352.82 5380.29,2352.82 5380.29,2385.98 5347.14,2385.98 5347.14,2352.82 ; 5347.14,3131.9 5380.29,3131.9 5363.72,3098.74 5347.14,3131.9 ; 5347.14,3471.7 5363.72,3479.99 5380.29,3471.7 5372.01,3488.28 5380.29,3504.86 5363.72,3496.57 5347.14,3504.86 5355.43,3488.28 5347.14,3471.7
  lines w12: 5286,2180.16 8517.49,2180.16 ; 5286,3547.68 8517.49,3547.68 ; 5623.86,2055.84 5623.86,3672 ; 5955.86,2055.84 5955.86,3672 ; 6592.43,2055.84 6592.43,3672 ; 6851.57,2055.84 6851.57,3672 ; 7226.72,2055.84 7226.72,3672 ; 7951.05,2055.84 7951.05,3672 ; 5286,2055.84 8517.49,2055.84 8517.49,3672 5286,3672 5286,2055.84
  text "Symbol" at 5360.59,3584.97 h72
  text "Quantity" at 5661.16,3584.97 h72
  text "Finished Hole Size" at 5993.16,3584.97 h72
  text "Plated" at 6629.72,3584.97 h72
  text "Hole Type" at 6888.86,3584.97 h72
  text "Drill Layer Pair" at 7264.02,3584.97 h72
  text "Hole Tolerance" at 7988.35,3584.97 h72
  text "428" at 5661.16,3460.65 h60
  text "7.87mil (0.200mm)" at 5993.16,3460.65 h60
  text "PTH" at 6629.72,3460.65 h60
  text "Round" at 6888.86,3460.65 h60
  text "Top Layer - Bottom Layer" at 7264.02,3460.65 h60
  text "1" at 5661.16,3336.33 h60
  text "8.00mil (0.203mm)" at 5993.16,3336.33 h60
  text "PTH" at 6629.72,3336.33 h60
  text "Round" at 6888.86,3336.33 h60
  text "Top Layer - Bottom Layer" at 7264.02,3336.33 h60
  text "780" at 5661.16,3212.01 h60
  text "10.00mil (0.254mm)" at 5993.16,3212.01 h60
  text "PTH" at 6629.72,3212.01 h60
  text "Round" at 6888.86,3212.01 h60
  text "Top Layer - Bottom Layer" at 7264.02,3212.01 h60
  text "4" at 5661.16,3087.69 h60
  text "37.40mil (0.950mm)" at 5993.16,3087.69 h60
  text "PTH" at 6629.72,3087.69 h60
  text "Round" at 6888.86,3087.69 h60
  text "Top Layer - Bottom Layer" at 7264.02,3087.69 h60
  text "4" at 5661.16,2963.37 h60
  text "40.00mil (1.016mm)" at 5993.16,2963.37 h60
  text "PTH" at 6629.72,2963.37 h60
  text "Round" at 6888.86,2963.37 h60
  text "Top Layer - Bottom Layer" at 7264.02,2963.37 h60
  text "40" at 5661.16,2839.05 h60
  text "40.16mil (1.020mm)" at 5993.16,2839.05 h60
  text "PTH" at 6629.72,2839.05 h60
  text "Round" at 6888.86,2839.05 h60
  text "Top Layer - Bottom Layer" at 7264.02,2839.05 h60
  text "6" at 5661.16,2714.73 h60
  text "45.28mil (1.150mm)" at 5993.16,2714.73 h60
  text "PTH" at 6629.72,2714.73 h60
  text "Round" at 6888.86,2714.73 h60
  text "Top Layer - Bottom Layer" at 7264.02,2714.73 h60
  text "5" at 5661.16,2590.41 h60
  text "47.24mil (1.200mm)" at 5993.16,2590.41 h60
  text "PTH" at 6629.72,2590.41 h60
  text "Round" at 6888.86,2590.41 h60
  text "Top Layer - Bottom Layer" at 7264.02,2590.41 h60
  text "2" at 5661.16,2466.09 h60
  text "51.18mil (1.300mm)" at 5993.16,2466.09 h60
  text "PTH" at 6629.72,2466.09 h60
  text "Round" at 6888.86,2466.09 h60
  text "Top Layer - Bottom Layer" at 7264.02,2466.09 h60
  text "5" at 5661.16,2341.77 h60
  text "51.18mil (1.300mm)" at 5993.16,2341.77 h60
  text "PTH" at 6629.72,2341.77 h60
  text "Round" at 6888.86,2341.77 h60
  text "Top Layer - Bottom Layer" at 7264.02,2341.77 h60
  text "+/-3.94mil" at 7988.35,2341.77 h60
  text "4" at 5661.16,2217.45 h60
  text "125.98mil (3.200mm)" at 5993.16,2217.45 h60
  text "PTH" at 6629.72,2217.45 h60
  text "Round" at 6888.86,2217.45 h60
  text "Top Layer - Bottom Layer" at 7264.02,2217.45 h60
  text "1279 Total" at 5661.16,2093.13 h60
  text ".Layer_Name" at 577,-858.49 h60
M17 Embedded Cavity:
  text ".Layer_Name" at 577,-858.49 h60
M18 Embedded Assembly:
  text ".Layer_Name" at 577,-858.49 h60
M19 Embedded Keepout:
  text ".Layer_Name" at 577,-858.49 h60

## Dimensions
0,-400 to 1000,-400 on M2 Board Dimensions
0,0 to 0,4750 on M2 Board Dimensions
0,0 to 3650,0 on M2 Board Dimensions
